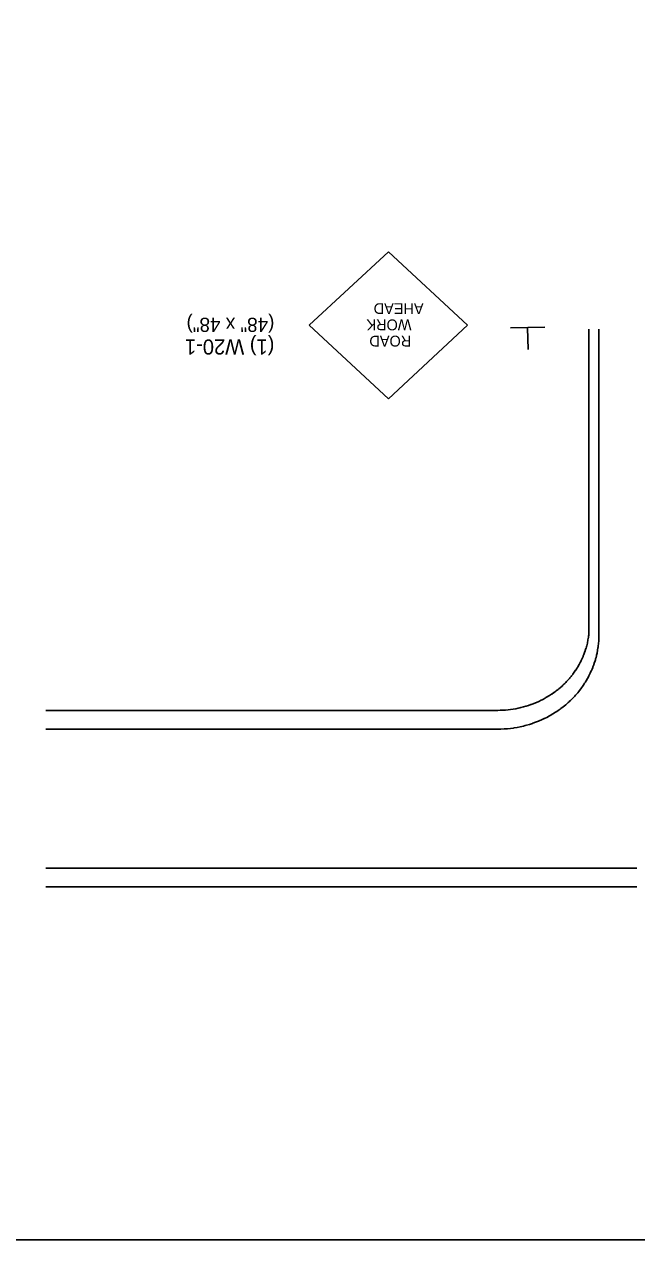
# Model space of a CAD drawing. Extents: x 1416408 to 1429341, y 372694 to 383211.
# Drawn here: x 1417036 to 1417480, y 376066 to 376949 of the extents above; entities that cross this region are included whole.
import ezdxf

# ---------------------------------------------------------------- set-up
doc = ezdxf.new("R2010")
doc.units = 0
for name, color, linetype in [('Default', 7, 'Continuous'), ('DSN_DRFT_Junk-No-Plot', 7, 'Continuous'), ('R_MOT', 7, 'Continuous'), ('R_Proposed Road', 7, 'Continuous')]:
    doc.layers.add(name, color=color, linetype=linetype)

msp = doc.modelspace()

# ---------------------------------------------------------------- linework, layer by layer
at = {"layer": 'Default'}
msp.add_lwpolyline([(1416407.68, 377826.46), (1416407.68, 376066.46), (1419127.68, 376066.46), (1419127.68, 377826.46)], close=True, dxfattribs=at)
at = {"layer": 'DSN_DRFT_Junk-No-Plot'}
msp.add_lwpolyline([(1416407.68, 377826.46), (1419127.68, 377826.46), (1419127.68, 376066.46), (1416407.68, 376066.46)], close=True, dxfattribs=at)
at = {"layer": 'R_MOT'}
for p, q in [((1417242.63, 376730.44), (1417300.11, 376783.82)), ((1417300.11, 376783.82), (1417357.6, 376730.44)), ((1417242.63, 376730.44), (1417300.11, 376677.01)), ((1417300.11, 376677.01), (1417357.6, 376730.44)), ((1417388.9, 376728.63), (1417413.72, 376729.01)), ((1417401.25, 376728.49), (1417401.54, 376712.74))]:
    msp.add_line(p, q, dxfattribs=at)
at = {"layer": 'R_Proposed Road'}
for p, q in [((1417445.68, 376661.82), (1417445.68, 376727.54)), ((1417453.03, 376661.77), (1417453.03, 376727.54))]:
    msp.add_line(p, q, dxfattribs=at)
for points in [[(1417379.5, 376437.13), (1417381.86, 376437.16), (1417384.21, 376437.27), (1417386.56, 376437.44), (1417388.9, 376437.69), (1417391.09, 376437.98), (1417391.24, 376438), (1417393.56, 376438.39), (1417395.86, 376438.84), (1417398.15, 376439.36), (1417399.45, 376439.69), (1417400.42, 376439.95), (1417402.67, 376440.61), (1417404.89, 376441.33), (1417405.09, 376441.4), (1417407.09, 376442.12), (1417409.26, 376442.98), (1417409.58, 376443.11), (1417411.4, 376443.9), (1417413.38, 376444.82), (1417413.51, 376444.88), (1417415.58, 376445.92), (1417416.71, 376446.52), (1417417.62, 376447.03), (1417419.61, 376448.19), (1417419.68, 376448.23), (1417421.57, 376449.42), (1417422.36, 376449.94), (1417423.48, 376450.7), (1417424.82, 376451.65), (1417425.34, 376452.04), (1417427.07, 376453.36), (1417427.16, 376453.43), (1417428.93, 376454.88), (1417429.16, 376455.07), (1417430.65, 376456.38), (1417431.09, 376456.78), (1417431.49, 376457.14), (1417432.32, 376457.92), (1417432.89, 376458.48), (1417433.93, 376459.52), (1417434.58, 376460.19), (1417435.49, 376461.17), (1417436.15, 376461.9), (1417436.99, 376462.86), (1417437.62, 376463.61), (1417438.43, 376464.59), (1417439, 376465.32), (1417439.81, 376466.37), (1417440.29, 376467.03), (1417441.12, 376468.19), (1417441.5, 376468.73), (1417442.38, 376470.04), (1417442.64, 376470.44), (1417443.18, 376471.3), (1417443.57, 376471.93), (1417443.7, 376472.15), (1417444.69, 376473.86), (1417444.69, 376473.86), (1417445.62, 376475.57), (1417445.75, 376475.82), (1417446.48, 376477.28), (1417446.73, 376477.8), (1417447.28, 376478.99), (1417447.65, 376479.82), (1417448.03, 376480.69), (1417448.5, 376481.86), (1417448.71, 376482.4), (1417449.28, 376483.93), (1417449.35, 376484.11), (1417449.92, 376485.82), (1417449.99, 376486.02), (1417450.45, 376487.53), (1417450.62, 376488.13), (1417450.92, 376489.24), (1417451.18, 376490.26), (1417451.35, 376490.94), (1417451.67, 376492.4), (1417451.72, 376492.65), (1417452.05, 376494.36), (1417452.09, 376494.56), (1417452.33, 376496.07), (1417452.42, 376496.73), (1417452.56, 376497.78), (1417452.69, 376498.9), (1417452.75, 376499.49), (1417452.88, 376501.09), (1417452.88, 376501.2), (1417452.98, 376502.9), (1417452.99, 376503.28), (1417453.02, 376504.61), (1417453.03, 376505.47), (1417453.03, 376506.32), (1417453.03, 376508.03), (1417453.03, 376509.74), (1417453.03, 376511.45), (1417453.03, 376513.15), (1417453.03, 376514.86), (1417453.03, 376516.57), (1417453.03, 376518.28), (1417453.03, 376519.99), (1417453.03, 376521.7), (1417453.03, 376523.41), (1417453.03, 376525.11), (1417453.03, 376526.82), (1417453.03, 376528.53), (1417453.03, 376530.24), (1417453.03, 376531.95), (1417453.03, 376533.66), (1417453.03, 376535.36), (1417453.03, 376537.07), (1417453.03, 376538.78), (1417453.03, 376540.49), (1417453.03, 376542.2), (1417453.03, 376543.91), (1417453.03, 376545.61), (1417453.03, 376547.32), (1417453.03, 376549.03), (1417453.03, 376550.74), (1417453.03, 376552.45), (1417453.03, 376554.16), (1417453.03, 376555.87), (1417453.03, 376557.57), (1417453.03, 376559.28), (1417453.03, 376560.99), (1417453.03, 376562.7), (1417453.03, 376564.41), (1417453.03, 376566.12), (1417453.03, 376567.82), (1417453.03, 376569.53), (1417453.03, 376571.24), (1417453.03, 376572.95), (1417453.03, 376574.66), (1417453.03, 376576.37), (1417453.03, 376578.08), (1417453.03, 376579.78), (1417453.03, 376581.49), (1417453.03, 376583.2), (1417453.03, 376584.91), (1417453.03, 376586.62), (1417453.03, 376588.33), (1417453.03, 376590.03), (1417453.03, 376591.74), (1417453.03, 376593.45), (1417453.03, 376595.16), (1417453.03, 376596.87), (1417453.03, 376598.58), (1417453.03, 376600.29), (1417453.03, 376601.99), (1417453.03, 376603.7), (1417453.03, 376605.41), (1417453.03, 376607.12), (1417453.03, 376608.83), (1417453.03, 376610.54), (1417453.03, 376612.24), (1417453.03, 376613.95), (1417453.03, 376615.66), (1417453.03, 376617.37), (1417453.03, 376619.08), (1417453.03, 376620.79), (1417453.03, 376622.5), (1417453.03, 376624.2), (1417453.03, 376625.91), (1417453.03, 376627.62), (1417453.03, 376629.33), (1417453.03, 376631.04), (1417453.03, 376632.75), (1417453.03, 376634.45), (1417453.03, 376636.16), (1417453.03, 376637.87), (1417453.03, 376639.58), (1417453.03, 376641.29), (1417453.03, 376642.14), (1417453.03, 376643), (1417453.03, 376644.71), (1417453.03, 376646.41), (1417453.03, 376648.12), (1417453.03, 376649.83), (1417453.03, 376651.54), (1417453.03, 376653.25), (1417453.03, 376654.96), (1417453.03, 376656.66), (1417453.03, 376657.92), (1417453.03, 376658.38), (1417453.03, 376660.09), (1417453.03, 376661.77)], [(1417379.5, 376450.8), (1417381.39, 376450.82), (1417383.27, 376450.89), (1417385.15, 376451.02), (1417387.03, 376451.19), (1417388.79, 376451.39), (1417388.9, 376451.41), (1417390.77, 376451.68), (1417392.63, 376452), (1417394.48, 376452.37), (1417395.53, 376452.6), (1417396.32, 376452.78), (1417398.15, 376453.25), (1417399.97, 376453.76), (1417400.13, 376453.81), (1417401.78, 376454.33), (1417403.56, 376454.94), (1417403.83, 376455.03), (1417405.34, 376455.6), (1417406.99, 376456.26), (1417407.09, 376456.31), (1417408.83, 376457.06), (1417409.78, 376457.5), (1417410.55, 376457.87), (1417412.24, 376458.72), (1417412.3, 376458.75), (1417413.91, 376459.62), (1417414.59, 376460.01), (1417415.56, 376460.56), (1417416.72, 376461.27), (1417417.18, 376461.56), (1417418.69, 376462.54), (1417418.77, 376462.6), (1417420.33, 376463.68), (1417420.53, 376463.82), (1417421.86, 376464.81), (1417422.26, 376465.11), (1417422.62, 376465.39), (1417423.36, 376465.99), (1417423.88, 376466.41), (1417424.83, 376467.21), (1417425.42, 376467.72), (1417426.26, 376468.47), (1417426.87, 376469.03), (1417427.65, 376469.78), (1417428.25, 376470.36), (1417429.01, 376471.12), (1417429.55, 376471.69), (1417430.32, 376472.52), (1417430.79, 376473.03), (1417431.6, 376473.95), (1417431.97, 376474.38), (1417432.83, 376475.42), (1417433.09, 376475.74), (1417433.63, 376476.42), (1417434.02, 376476.93), (1417434.15, 376477.11), (1417435.16, 376478.48), (1417435.16, 376478.48), (1417436.11, 376479.87), (1417436.25, 376480.07), (1417437.02, 376481.26), (1417437.29, 376481.69), (1417437.88, 376482.66), (1417438.28, 376483.35), (1417438.69, 376484.07), (1417439.22, 376485.04), (1417439.46, 376485.49), (1417440.1, 376486.76), (1417440.18, 376486.91), (1417440.86, 376488.35), (1417440.93, 376488.52), (1417441.49, 376489.79), (1417441.71, 376490.31), (1417442.09, 376491.24), (1417442.42, 376492.12), (1417442.64, 376492.71), (1417443.07, 376493.96), (1417443.15, 376494.17), (1417443.62, 376495.65), (1417443.67, 376495.82), (1417444.04, 376497.14), (1417444.2, 376497.71), (1417444.43, 376498.63), (1417444.67, 376499.62), (1417444.78, 376500.14), (1417445.07, 376501.55), (1417445.09, 376501.65), (1417445.35, 376503.17), (1417445.41, 376503.5), (1417445.58, 376504.7), (1417445.67, 376505.47), (1417445.67, 376506.32), (1417445.67, 376508.03), (1417445.67, 376509.74), (1417445.67, 376511.45), (1417445.67, 376513.15), (1417445.67, 376514.86), (1417445.67, 376516.57), (1417445.67, 376518.28), (1417445.67, 376519.99), (1417445.67, 376521.7), (1417445.67, 376523.41), (1417445.67, 376525.11), (1417445.67, 376526.82), (1417445.67, 376528.53), (1417445.67, 376530.24), (1417445.67, 376531.95), (1417445.67, 376533.66), (1417445.67, 376535.36), (1417445.67, 376537.07), (1417445.67, 376538.78), (1417445.67, 376540.49), (1417445.67, 376542.2), (1417445.67, 376543.91), (1417445.67, 376545.61), (1417445.67, 376547.32), (1417445.67, 376549.03), (1417445.67, 376550.74), (1417445.67, 376552.45), (1417445.67, 376554.16), (1417445.67, 376555.87), (1417445.67, 376557.57), (1417445.67, 376559.28), (1417445.67, 376560.99), (1417445.67, 376562.7), (1417445.67, 376564.41), (1417445.67, 376566.12), (1417445.67, 376567.82), (1417445.67, 376569.53), (1417445.67, 376571.24), (1417445.67, 376572.95), (1417445.67, 376574.66), (1417445.67, 376576.37), (1417445.67, 376578.08), (1417445.67, 376579.78), (1417445.67, 376581.49), (1417445.67, 376583.2), (1417445.67, 376584.91), (1417445.67, 376586.62), (1417445.67, 376588.33), (1417445.67, 376590.03), (1417445.67, 376591.74), (1417445.67, 376593.45), (1417445.67, 376595.16), (1417445.67, 376596.87), (1417445.67, 376598.58), (1417445.67, 376600.29), (1417445.67, 376601.99), (1417445.67, 376603.7), (1417445.67, 376605.41), (1417445.67, 376607.12), (1417445.67, 376608.83), (1417445.67, 376610.54), (1417445.67, 376612.24), (1417445.67, 376613.95), (1417445.67, 376615.66), (1417445.67, 376617.37), (1417445.67, 376619.08), (1417445.67, 376620.79), (1417445.67, 376622.5), (1417445.67, 376624.2), (1417445.67, 376625.91), (1417445.67, 376627.62), (1417445.67, 376629.33), (1417445.67, 376631.04), (1417445.67, 376632.75), (1417445.67, 376634.45), (1417445.67, 376636.16), (1417445.67, 376637.87), (1417445.67, 376639.58), (1417445.67, 376641.29), (1417445.67, 376642.14), (1417445.67, 376643), (1417445.67, 376644.71), (1417445.67, 376646.41), (1417445.67, 376648.12), (1417445.67, 376649.83), (1417445.67, 376651.54), (1417445.67, 376653.25), (1417445.67, 376654.96), (1417445.67, 376656.66), (1417445.67, 376657.92), (1417445.67, 376658.38), (1417445.68, 376660.1), (1417445.68, 376661.77)], [(1417379.5, 376450.8), (1417370.31, 376450.8), (1417351.93, 376450.8), (1417333.55, 376450.8), (1417315.16, 376450.8), (1417296.78, 376450.8), (1417278.4, 376450.8), (1417263.72, 376450.8), (1417260.02, 376450.8), (1417241.64, 376450.8), (1417223.25, 376450.8), (1417204.87, 376450.8), (1417186.49, 376450.8), (1417168.11, 376450.8), (1417149.73, 376450.8), (1417131.34, 376450.8), (1417129.07, 376450.8), (1417112.96, 376450.8), (1417094.58, 376450.8), (1417076.2, 376450.8), (1417057.82, 376450.8), (1417051.26, 376450.8)], [(1417379.5, 376437.13), (1417370.31, 376437.13), (1417351.93, 376437.13), (1417333.55, 376437.13), (1417315.16, 376437.13), (1417296.78, 376437.13), (1417278.4, 376437.13), (1417263.72, 376437.13), (1417260.02, 376437.13), (1417241.64, 376437.13), (1417223.25, 376437.13), (1417204.87, 376437.13), (1417186.49, 376437.13), (1417168.11, 376437.13), (1417149.73, 376437.13), (1417131.34, 376437.13), (1417129.07, 376437.13), (1417112.96, 376437.13), (1417094.58, 376437.13), (1417076.2, 376437.13), (1417057.82, 376437.13), (1417051.26, 376437.13)], [(1417480.6, 376336.33), (1417471.41, 376336.33), (1417462.22, 376336.33), (1417443.84, 376336.33), (1417425.45, 376336.33), (1417407.07, 376336.33), (1417398.38, 376336.33), (1417398.38, 376336.33), (1417388.69, 376336.33), (1417370.31, 376336.33), (1417351.93, 376336.33), (1417333.55, 376336.33), (1417315.16, 376336.33), (1417296.78, 376336.33), (1417278.4, 376336.33), (1417263.72, 376336.33), (1417260.02, 376336.33), (1417241.64, 376336.33), (1417223.25, 376336.33), (1417204.87, 376336.33), (1417186.49, 376336.33), (1417168.11, 376336.33), (1417149.73, 376336.33), (1417131.34, 376336.33), (1417129.07, 376336.33), (1417112.96, 376336.33), (1417094.58, 376336.33), (1417076.2, 376336.33), (1417057.82, 376336.33), (1417051.26, 376336.33)], [(1417480.6, 376322.66), (1417471.41, 376322.66), (1417462.22, 376322.66), (1417443.84, 376322.66), (1417425.45, 376322.66), (1417407.07, 376322.66), (1417398.38, 376322.66), (1417398.38, 376322.66), (1417388.69, 376322.66), (1417370.31, 376322.66), (1417351.93, 376322.66), (1417333.55, 376322.66), (1417315.16, 376322.66), (1417296.78, 376322.66), (1417278.4, 376322.66), (1417263.72, 376322.66), (1417260.02, 376322.66), (1417241.64, 376322.66), (1417223.25, 376322.66), (1417204.87, 376322.66), (1417186.49, 376322.66), (1417168.11, 376322.66), (1417149.73, 376322.66), (1417131.34, 376322.66), (1417129.07, 376322.66), (1417112.96, 376322.66), (1417094.58, 376322.66), (1417076.2, 376322.66), (1417057.82, 376322.66), (1417051.26, 376322.66)]]:
    msp.add_lwpolyline(points, dxfattribs=at)

# ---------------------------------------------------------------- texts
at = {"layer": 'R_MOT'}
for s, height, rotation, p in [('(48" x 48")', 10.2497, 180, (1417217.33, 376735.83)), (' AHEAD ', 7.871, 180.00053, (1417328.62, 376746.44)), ('WORK', 7.87, 180.00003, (1417316.89, 376734.63)), ('(1) W20-1', 10.934, 180, (1417217.33, 376720.1)), ('ROAD', 7.871, 180.00042, (1417316.72, 376722.82))]:
    msp.add_text(s, height=height, rotation=rotation, dxfattribs=at).set_placement(p)

doc.saveas('drawing.dxf')
